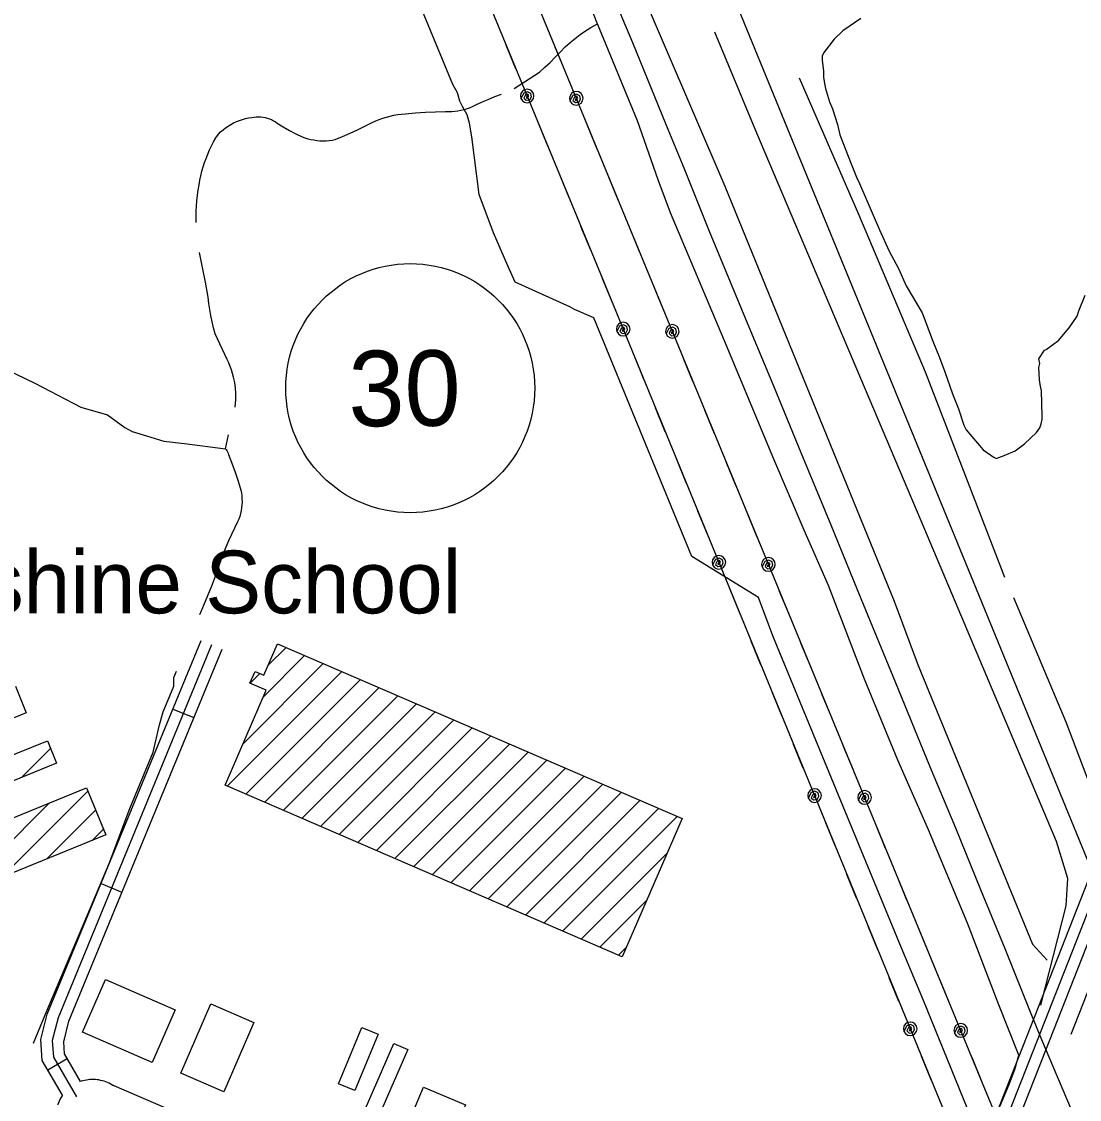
# Model space of a CAD drawing. Extents: x 3329332 to 3367211, y 631066 to 656469.
# Drawn here: x 3347758 to 3349160, y 652972 to 654400 of the extents above; entities that cross this region are included whole.
import ezdxf

# ---------------------------------------------------------------- set-up
doc = ezdxf.new("R2010")
doc.units = 0
for name, color, linetype in [('V-BLDG-IDEN', 7, 'Continuous'), ('V-BLDG-OTLN', 7, 'Continuous'), ('V-RAIL-TRAK', 7, 'Continuous'), ('V-ROAD-CNTR', 7, 'Continuous'), ('V-ROAD-IDEN', 7, 'Continuous'), ('V-SITE-VEGE', 7, 'Continuous'), ('V-TOPO-SHOR', 7, 'Continuous'), ('V-UTIL-LINE', 7, 'Continuous')]:
    doc.layers.add(name, color=color, linetype=linetype)

msp = doc.modelspace()

# ---------------------------------------------------------------- linework, layer by layer
at = {"layer": 'V-BLDG-OTLN'}
for p, q in [((3348085.1, 653547.4), (3348108.7, 653571)), ((3348078.7, 653505.6), (3348133.4, 653560.3)), ((3348030.8, 653387), (3348182.8, 653539)), ((3348051.8, 653443.4), (3348158.1, 653549.6)), ((3348055.5, 653376.4), (3348207.5, 653528.3)), ((3348061.1, 653523.4), (3348074.2, 653536.4)), ((3348080.2, 653365.7), (3348232.2, 653517.7)), ((3348104.9, 653355), (3348256.9, 653507)), ((3348129.6, 653344.4), (3348281.6, 653496.3)), ((3348154.3, 653333.7), (3348306.2, 653485.7)), ((3348179, 653323), (3348330.9, 653475)), ((3348203.7, 653312.4), (3348355.6, 653464.3)), ((3348228.4, 653301.7), (3348380.3, 653453.7)), ((3348253.1, 653291.1), (3348405, 653443)), ((3347758.7, 653399.1), (3347796.7, 653437.1)), ((3348277.7, 653280.4), (3348429.7, 653432.3)), ((3348302.4, 653269.7), (3348454.4, 653421.7)), ((3348327.1, 653259.1), (3348479.1, 653411)), ((3348351.8, 653248.4), (3348503.8, 653400.4)), ((3348376.5, 653237.7), (3348528.5, 653389.7)), ((3347732.2, 653266.5), (3347846.2, 653380.4)), ((3348401.2, 653227.1), (3348553.2, 653379)), ((3348425.9, 653216.4), (3348577.9, 653368.4)), ((3347672.4, 653242), (3347795.3, 653365)), ((3347791.9, 653290.9), (3347856.4, 653355.3)), ((3348450.6, 653205.8), (3348602.5, 653357.7)), ((3348475.3, 653195.1), (3348627.2, 653347)), ((3347851.7, 653315.3), (3347866.7, 653330.2)), ((3348500, 653184.4), (3348613.7, 653298.2)), ((3348524.7, 653173.8), (3348586.9, 653236)), ((3348549.4, 653163.1), (3348560, 653173.7))]:
    msp.add_line(p, q, dxfattribs=at)
for points in [[(3348633.6, 653344.3), (3348554.4, 653160.9), (3348028, 653388.3), (3348082.4, 653514.2), (3348060.9, 653523.4), (3348067.7, 653539.2), (3348079.4, 653534.2), (3348097.4, 653575.9)], [(3347961.9, 653091), (3347931.5, 653021), (3347839, 653061.2), (3347869.4, 653131.2)], [(3347969.4, 653007.1), (3348009.1, 653098.6), (3348066.1, 653073.9), (3348026.4, 652982.4)], [(3348230.8, 653058.4), (3348200.1, 652983.9), (3348178.4, 652992.9), (3348209.1, 653067.4)], [(3348210, 652900.6), (3348191.6, 652908.6), (3348251.6, 653046.4), (3348270, 653038.4)], [(3348307.8, 652872.6), (3348251.9, 652896.1), (3348290.7, 652988.5), (3348346.6, 652965.1)]]:
    msp.add_lwpolyline(points, close=True, dxfattribs=at)
for points in [[(3347750.1, 653519.6), (3347764.5, 653484.4), (3347586.4, 653411.6)], [(3347603, 653370.9), (3347792.6, 653447.4), (3347804.3, 653417.7), (3347617, 653341.2)], [(3347634.2, 653299.1), (3347844.3, 653385), (3347869.8, 653322.7), (3347657.6, 653236)]]:
    msp.add_lwpolyline(points, dxfattribs=at)
at = {"layer": 'V-RAIL-TRAK'}
msp.add_lwpolyline([(3349202.3, 652830.4), (3349149.9, 652958.2), (3349131.3, 653002), (3349110.4, 653051.1), (3349097.1, 653083.5), (3349061.9, 653171.5), (3349029.7, 653249.6), (3348996.3, 653331.3), (3348961.9, 653413.5), (3348916.5, 653524.8), (3348871.1, 653635.3), (3348831, 653732.9), (3348791.3, 653828.8), (3348755.2, 653916.9), (3348720.3, 654000.4), (3348670.1, 654121.8), (3348637.1, 654203.5), (3348611.9, 654264.7), (3348568.3, 654371.9), (3348523.8, 654477.8), (3348478.8, 654587.8), (3348449, 654660.4)], dxfattribs=at)
at = {"layer": 'V-ROAD-CNTR'}
for p, q in [((3347958.8, 653489.3), (3347986.5, 653477.9)), ((3347863.5, 653258.2), (3347891.2, 653246.8)), ((3347792.8, 653011.4), (3347818.7, 653026.4))]:
    msp.add_line(p, q, dxfattribs=at)
for points in [[(3348890.1, 652554.7), (3348987.6, 652793.7), (3349357.8, 653734.5), (3349739.4, 654671.6)], [(3347836.6, 649939.1), (3348422, 651367.8), (3349001.5, 652788.1), (3349371.7, 653728.9), (3349753.3, 654665.9)], [(3347850.5, 649933.4), (3348435.9, 651362.1), (3349015.5, 652782.6), (3349385.7, 653723.3), (3349767.2, 654660.2)], [(3348607.1, 654663.7), (3348622.3, 654626.9), (3349428.4, 652661.2), (3350055.8, 651140.1)], [(3347812.3, 652977.6), (3347785.7, 653023.7), (3347783.7, 653051.3), (3347792.2, 653085.1), (3347996.2, 653580.1)], [(3348010, 653574.4), (3347806.5, 653080.4), (3347798.9, 653050), (3347800.4, 653028.2), (3347830.8, 652975.6)], [(3347836.4, 652995.8), (3347815.1, 653032.7), (3347814, 653048.6), (3347820.8, 653075.7), (3348023.9, 653568.7)], [(3347880, 652990.1), (3347878.4, 652991.2), (3347876.3, 652992.4), (3347874.2, 652993.5), (3347872.1, 652994.5), (3347869.9, 652995.4), (3347867.6, 652996.2), (3347865.3, 652996.9), (3347863, 652997.4), (3347860.7, 652997.9), (3347858.3, 652998.2), (3347856, 652998.5), (3347853.6, 652998.6), (3347851.2, 652998.6), (3347848.8, 652998.4), (3347846.5, 652998.2), (3347844.1, 652997.8), (3347841.8, 652997.4), (3347839.5, 652996.8), (3347837.2, 652996.1), (3347836.4, 652995.8)], [(3348890.1, 652554.7), (3347877.8, 652991.3)], [(3347812.3, 652977.6), (3347810.2, 652974.1), (3347809, 652972), (3347808, 652969.9), (3347807.1, 652967.7), (3347806.3, 652965.6), (3347806, 652964.6)]]:
    msp.add_lwpolyline(points, dxfattribs=at)
at = {"layer": 'V-ROAD-IDEN'}
msp.add_circle((3348273.3, 653914.4), 165, dxfattribs=at)
at = {"layer": 'V-SITE-VEGE'}
msp.add_lwpolyline([(3348870.6, 654404.3), (3348846.5, 654388), (3348835, 654376.7), (3348821.3, 654359.3), (3348819.2, 654354.1), (3348819.1, 654348.9), (3348821, 654334.4), (3348820.9, 654326.1), (3348822.8, 654315.7), (3348823.8, 654311.5), (3348828.8, 654293.9), (3348832.8, 654284.5), (3348839.8, 654263.6), (3348842.8, 654250.1), (3348857.8, 654211.6), (3348864.9, 654193.8), (3348868.9, 654185.5), (3348895.1, 654124), (3348908.2, 654095.8), (3348920.4, 654072.8), (3348930.5, 654049.9), (3348951.8, 654014.4), (3348965.9, 653976.9), (3348974.9, 653955), (3348982, 653936.2), (3348992, 653907.1), (3349000, 653887.2), (3349007, 653865.4), (3349010, 653859.1), (3349032.5, 653832.9), (3349042.8, 653825.5), (3349045.9, 653823.4), (3349050, 653821.3), (3349060.4, 653825.3), (3349075, 653831.3), (3349087.6, 653840.5), (3349103.3, 653855.9), (3349107.6, 653862), (3349109.7, 653867.2), (3349110.8, 653873.4), (3349110.9, 653877.6), (3349110.2, 653910.8), (3349108.3, 653919.1), (3349107.3, 653925.3), (3349106.5, 653941.9), (3349107.6, 653947.1), (3349106.6, 653953.3), (3349114, 653964.6), (3349116.1, 653965.7), (3349132.9, 653977.9), (3349141.3, 653988.2), (3349146.5, 653994.3), (3349157.1, 654009.7), (3349159.3, 654017), (3349167.8, 654037.6)], dxfattribs=at)
at = {"layer": 'V-TOPO-SHOR'}
msp.add_line((3348028.4, 653834.1), (3348032.3, 653852.8), dxfattribs=at)
for points in [[(3348934.8, 652665), (3348966.7, 652743.2), (3349000, 652827.6), (3349039.3, 652925.9), (3349066.6, 652991.1), (3349074.6, 653011.7), (3349080.1, 653030.9), (3349053.5, 653097.3), (3349012, 653205.8), (3348960, 653329.3), (3348919.7, 653421.8), (3348875.3, 653528.9), (3348827.6, 653652.9), (3348795.3, 653726.5), (3348754.1, 653823.5), (3348693.3, 653968.8), (3348618.4, 654146.6), (3348602, 654190.2), (3348574.6, 654268.6), (3348521.5, 654397.3), (3348521.3, 654397.9), (3348469.9, 654529.7), (3348439.4, 654597.5), (3348413.5, 654660.4)], [(3348485.3, 654660), (3348690.3, 654182.2), (3348914.5, 653632.1), (3348946.5, 653547.2), (3349098.1, 653177.6), (3349117.3, 653156.4)], [(3348411.2, 654311.5), (3348444.8, 654333.1), (3348451.9, 654339.5), (3348458.8, 654346), (3348465.6, 654352.8), (3348472.1, 654359.7), (3348478.5, 654366.8), (3348485.1, 654372.4), (3348491.8, 654377.7), (3348498.7, 654382.9), (3348505.7, 654387.9), (3348512.9, 654392.1), (3348521.5, 654397.3)], [(3349108.9, 653096.9), (3349142.7, 653228.7), (3349144.7, 653264.8), (3349129.7, 653313.7), (3348950.4, 653738.5), (3348732.6, 654252.4), (3348677.1, 654386.2)], [(3348788.6, 654325.7), (3348867.4, 654144.8), (3348955.7, 653936), (3349044.4, 653706.6), (3349061.1, 653663.9)], [(3347989.7, 654134.1), (3347989.6, 654141.3), (3347989.8, 654148.4), (3347990.1, 654155.6), (3347990.7, 654162.7), (3347991.5, 654169.9), (3347992.4, 654176.9), (3347993.6, 654184), (3347994.6, 654189.9), (3347995.9, 654195.8), (3347997.3, 654201.7), (3347998.9, 654207.5), (3348000.8, 654213.2), (3348002.8, 654218.9), (3348005, 654224.5), (3348007.4, 654230), (3348010, 654235.4), (3348012.8, 654240.7), (3348015.8, 654246), (3348019, 654251.1), (3348022, 654254), (3348025.2, 654256.7), (3348028.6, 654259.3), (3348032, 654261.6), (3348035.6, 654263.8), (3348039.3, 654265.8), (3348043.2, 654267.5), (3348047.1, 654269.1), (3348051.1, 654270.4), (3348055.1, 654271.5), (3348059.2, 654272.4), (3348063.4, 654273), (3348066.3, 654273.5), (3348069.2, 654273.9), (3348072.2, 654274), (3348075.1, 654273.9), (3348078.1, 654273.6), (3348081, 654273), (3348083.9, 654272.3), (3348086.7, 654271.3), (3348089.4, 654270.2), (3348092, 654268.8), (3348094.6, 654267.2), (3348097, 654265.5), (3348105, 654260.6), (3348113.2, 654255.9), (3348121.6, 654251.4), (3348130, 654247.2), (3348133.8, 654245.9), (3348137.7, 654244.8), (3348141.6, 654243.9), (3348145.6, 654243.2), (3348149.6, 654242.7), (3348153.6, 654242.3), (3348157.6, 654242.2), (3348161.7, 654242.3), (3348165.7, 654242.6), (3348169.7, 654243.1), (3348173.7, 654243.8), (3348183.7, 654247.9), (3348193.7, 654252.3), (3348203.6, 654256.8), (3348213.3, 654261.5), (3348223, 654266.4), (3348227.6, 654268.5), (3348232.3, 654270.4), (3348237.1, 654272.1), (3348242, 654273.6), (3348246.9, 654274.9), (3348251.8, 654276), (3348256.8, 654276.9), (3348261.8, 654277.5), (3348266.9, 654278), (3348280.2, 654279.1), (3348293.5, 654280), (3348306.8, 654280.6), (3348320.2, 654281), (3348324.2, 654280.9), (3348328.3, 654281), (3348332.3, 654281.3), (3348336.3, 654281.9), (3348340.3, 654282.6), (3348344.2, 654283.5), (3348348.1, 654284.7), (3348352, 654286), (3348355.7, 654287.6), (3348359.4, 654289.3), (3348368, 654293.3), (3348376.7, 654297), (3348385.6, 654300.6), (3348394.5, 654303.8)], [(3348041.1, 653889.3), (3348041.7, 653894.1), (3348042.1, 653899), (3348042.2, 653903.9), (3348042.2, 653908.8), (3348041.7, 653913.9), (3348041.1, 653918.9), (3348040.2, 653923.9), (3348039.1, 653928.8), (3348037.9, 653933.7), (3348036.4, 653938.6), (3348034.7, 653943.3), (3348032.8, 653948), (3348030.7, 653952.6), (3348014.9, 653986.5), (3348012.8, 653994.5), (3348010.9, 654002.5), (3348009.2, 654010.5), (3348007.7, 654018.6), (3348006.5, 654026.8), (3348005.5, 654034.9), (3348002, 654054.7), (3347998.2, 654074.4), (3347994.1, 654094.1)], [(3347492.4, 654033.8), (3347725.8, 653945), (3347776, 653921.2), (3347836.9, 653889.1), (3347872.2, 653879.1), (3347895.2, 653862.4), (3347904.7, 653856.9), (3347923.7, 653851.2), (3347946.8, 653844.1), (3347974, 653841), (3348028.4, 653834.1)], [(3348028.4, 653834.1), (3348029.2, 653833.2), (3348030.3, 653831.7), (3348031.2, 653830), (3348031.9, 653828.3), (3348032.4, 653826.5), (3348036.9, 653814.9), (3348041.1, 653803.1), (3348045.1, 653791.2), (3348048.8, 653779.3), (3348049.6, 653775.5), (3348050.1, 653771.6), (3348050.3, 653767.7), (3348050.4, 653763.8), (3348050.2, 653759.9), (3348049.8, 653756), (3348049.2, 653752.2), (3348048.4, 653748.4), (3348047.3, 653744.6), (3348046, 653740.9), (3348044.6, 653737.3), (3348040.4, 653729.1), (3348036.4, 653720.7), (3348032.6, 653712.3), (3348029, 653703.7), (3348025.6, 653695.1), (3348022.3, 653686.5), (3348019.3, 653677.7), (3348014.6, 653664.8), (3348009.8, 653652), (3348004.7, 653639.2), (3347999.4, 653626.6), (3347993.9, 653614)], [(3349072.7, 653637.2), (3349142.3, 653472.4), (3349178.3, 653377.1), (3349182.1, 653363.7), (3349185.3, 653355.1), (3349199.9, 653348.9)], [(3347774.2, 653046.8), (3347789.6, 653084.2), (3347816.4, 653148), (3347846.2, 653217.5), (3347874.5, 653284.6), (3347901.9, 653357.5), (3347932.8, 653432.3), (3347940.9, 653468.4), (3347946, 653485.7), (3347959.9, 653519.7), (3347960, 653531.3), (3347963.5, 653539.4)], [(3349149.4, 653058.7), (3349181.1, 653139.5), (3349195.9, 653154.4), (3349206.6, 653150.2), (3349260, 652999.4)]]:
    msp.add_lwpolyline(points, dxfattribs=at)
at = {"layer": 'V-UTIL-LINE'}
for points in [[(3348280.4, 654660.1), (3348528.6, 654058.4), (3349879.4, 650766.8)], [(3349947.4, 650765), (3349454, 651980.1), (3349114.1, 652794.4), (3348779, 653606), (3348344.2, 654660.2)], [(3349017.1, 652946.7), (3348953.7, 653103), (3348922, 653179.3), (3348754, 653586.3), (3348735, 653637.2), (3348646.5, 653691.5), (3348516.5, 654007.7), (3348491.2, 654018.6), (3348484.9, 654022.2), (3348412.3, 654054.8), (3348402.7, 654076.6), (3348383.7, 654120.2), (3348364.7, 654171.1), (3348355.1, 654247.4), (3348351.9, 654265.6), (3348348.7, 654276.5), (3348342.4, 654287.4), (3348339.2, 654294.7), (3348336, 654305.6), (3348329.7, 654316.5), (3348218.7, 654585.4)], [(3348413.4, 654337.6), (3348400.5, 654369)], [(3348478.5, 654334.5), (3348465.5, 654366)], [(3348428.3, 654301.5), (3348426.8, 654299.1), (3348429.1, 654299.2), (3348430.5, 654301.5), (3348429.1, 654304.1), (3348425.9, 654302.9), (3348424, 654298.7), (3348427.1, 654295.8), (3348431.9, 654296.3), (3348433.9, 654300.5), (3348433.1, 654304.9), (3348428.9, 654307.2), (3348423.7, 654305.4), (3348420, 654298.1), (3348421.9, 654295.2), (3348424.9, 654293.2), (3348428.3, 654292.5), (3348431.8, 654293.2), (3348434.7, 654295.1), (3348436.6, 654298.1), (3348437.3, 654301.5), (3348436.6, 654304.9), (3348434.7, 654307.9), (3348431.8, 654309.8), (3348428.3, 654310.5), (3348424.9, 654309.8), (3348422, 654307.9), (3348420, 654305), (3348419.3, 654301.5), (3348420, 654298.1)], [(3348493.4, 654298.5), (3348491.8, 654296.1), (3348494.1, 654296.1), (3348495.6, 654298.5), (3348494.1, 654301.1), (3348490.9, 654299.9), (3348489, 654295.6), (3348492.2, 654292.7), (3348497, 654293.3), (3348499, 654297.4), (3348498.2, 654301.8), (3348493.9, 654304.1), (3348488.7, 654302.3), (3348485, 654295), (3348487, 654292.1), (3348489.9, 654290.2), (3348493.3, 654289.5), (3348496.8, 654290.2), (3348499.7, 654292.1), (3348501.7, 654295), (3348502.4, 654298.5), (3348501.7, 654301.9), (3348499.7, 654304.8), (3348496.8, 654306.8), (3348493.4, 654307.5), (3348489.9, 654306.8), (3348487, 654304.8), (3348485.1, 654301.9), (3348484.4, 654298.5), (3348485, 654295)], [(3348456.2, 654234), (3348443.2, 654265.5)], [(3348521.2, 654231), (3348508.2, 654262.4)], [(3348484.4, 654165.6), (3348471.4, 654197.1)], [(3348549.4, 654162.6), (3348536.4, 654194)], [(3348512.6, 654097.2), (3348499.6, 654128.7)], [(3348577.6, 654094.2), (3348564.7, 654125.6)], [(3348540.8, 654028.8), (3348528.6, 654058.4), (3348527.8, 654060.2)], [(3348605.8, 654025.8), (3348592.9, 654057.2)], [(3348555.6, 653992.7), (3348554, 653990.3), (3348556.3, 653990.4), (3348557.8, 653992.7), (3348556.4, 653995.3), (3348553.2, 653994.1), (3348551.2, 653989.9), (3348554.4, 653986.9), (3348559.2, 653987.5), (3348561.2, 653991.7), (3348560.4, 653996.1), (3348556.1, 653998.3), (3348550.9, 653996.6), (3348547.2, 653989.3), (3348549.2, 653986.4), (3348552.1, 653984.4), (3348555.5, 653983.7), (3348559, 653984.4), (3348561.9, 653986.3), (3348563.9, 653989.2), (3348564.6, 653992.7), (3348563.9, 653996.1), (3348561.9, 653999), (3348559, 654001), (3348555.6, 654001.7), (3348552.1, 654001), (3348549.2, 653999.1), (3348547.3, 653996.2), (3348546.6, 653992.7), (3348547.2, 653989.3)], [(3348620.7, 653989.7), (3348619.1, 653987.3), (3348621.5, 653987.4), (3348622.9, 653989.7), (3348621.5, 653992.3), (3348618.3, 653991.1), (3348616.4, 653986.9), (3348619.5, 653983.9), (3348624.3, 653984.5), (3348626.3, 653988.7), (3348625.5, 653993.1), (3348621.3, 653995.3), (3348616.1, 653993.5), (3348612.4, 653986.3), (3348614.3, 653983.4), (3348617.3, 653981.4), (3348620.7, 653980.7), (3348624.1, 653981.4), (3348627.1, 653983.3), (3348629, 653986.2), (3348629.7, 653989.7), (3348629, 653993.1), (3348627.1, 653996.1), (3348624.2, 653998), (3348620.7, 653998.7), (3348617.3, 653998), (3348614.4, 653996.1), (3348612.4, 653993.2), (3348611.7, 653989.7), (3348612.4, 653986.3)], [(3348583.3, 653925.2), (3348570.4, 653956.6)], [(3348648.5, 653922.2), (3348635.6, 653953.7)], [(3348611.4, 653856.7), (3348598.5, 653888.2)], [(3348676.8, 653853.8), (3348663.8, 653885.2)], [(3348639.5, 653788.3), (3348626.5, 653819.7)], [(3348705, 653785.4), (3348692, 653816.8)], [(3348667.6, 653719.8), (3348654.6, 653751.3)], [(3348733.2, 653717), (3348720.2, 653748.4)], [(3348682.4, 653683.7), (3348680.8, 653681.3), (3348683.1, 653681.4), (3348684.6, 653683.7), (3348683.2, 653686.3), (3348680, 653685.1), (3348678, 653680.9), (3348681.2, 653678), (3348686, 653678.5), (3348688, 653682.7), (3348687.2, 653687.1), (3348682.9, 653689.3), (3348677.7, 653687.6), (3348674, 653680.3), (3348676, 653677.4), (3348678.9, 653675.4), (3348682.3, 653674.7), (3348685.8, 653675.4), (3348688.7, 653677.3), (3348690.7, 653680.2), (3348691.4, 653683.7), (3348690.7, 653687.1), (3348688.7, 653690.1), (3348685.8, 653692), (3348682.4, 653692.7), (3348678.9, 653692), (3348676, 653690.1), (3348674.1, 653687.2), (3348673.4, 653683.7), (3348674, 653680.3)], [(3348748.1, 653680.9), (3348746.5, 653678.5), (3348748.8, 653678.6), (3348750.3, 653681), (3348748.8, 653683.5), (3348745.6, 653682.4), (3348743.7, 653678.1), (3348746.9, 653675.2), (3348751.7, 653675.8), (3348753.7, 653679.9), (3348752.9, 653684.3), (3348748.6, 653686.6), (3348743.4, 653684.8), (3348739.7, 653677.5), (3348741.7, 653674.6), (3348744.6, 653672.6), (3348748, 653671.9), (3348751.5, 653672.6), (3348754.4, 653674.6), (3348756.4, 653677.5), (3348757.1, 653680.9), (3348756.4, 653684.4), (3348754.4, 653687.3), (3348751.5, 653689.2), (3348748.1, 653689.9), (3348744.6, 653689.3), (3348741.7, 653687.3), (3348739.8, 653684.4), (3348739.1, 653681), (3348739.7, 653677.5)], [(3348710.1, 653616.2), (3348697.2, 653647.6)], [(3348775.9, 653613.5), (3348762.9, 653644.9)], [(3348738.2, 653547.7), (3348725.3, 653579.2)], [(3348804.1, 653545.1), (3348791.2, 653576.5)], [(3348766.3, 653479.3), (3348753.3, 653510.7)], [(3348832.4, 653476.7), (3348819.4, 653508.1)], [(3348794.3, 653410.8), (3348781.4, 653442.3)], [(3348860.6, 653408.3), (3348847.6, 653439.7)], [(3348809.2, 653374.7), (3348807.6, 653372.3), (3348809.9, 653372.4), (3348811.4, 653374.7), (3348810, 653377.3), (3348806.8, 653376.2), (3348804.8, 653371.9), (3348808, 653369), (3348812.8, 653369.5), (3348814.8, 653373.7), (3348814, 653378.1), (3348809.7, 653380.4), (3348804.5, 653378.6), (3348800.8, 653371.3), (3348802.8, 653368.4), (3348805.7, 653366.4), (3348809.1, 653365.7), (3348812.6, 653366.4), (3348815.5, 653368.3), (3348817.5, 653371.2), (3348818.2, 653374.7), (3348817.5, 653378.1), (3348815.5, 653381.1), (3348812.6, 653383), (3348809.2, 653383.7), (3348805.7, 653383), (3348802.8, 653381.1), (3348800.9, 653378.2), (3348800.2, 653374.7), (3348800.8, 653371.3)], [(3348875.5, 653372.2), (3348873.9, 653369.8), (3348876.3, 653369.9), (3348877.7, 653372.2), (3348876.3, 653374.8), (3348873.1, 653373.6), (3348871.2, 653369.4), (3348874.3, 653366.5), (3348879.1, 653367), (3348881.1, 653371.2), (3348880.3, 653375.6), (3348876.1, 653377.8), (3348870.9, 653376.1), (3348867.2, 653368.8), (3348869.1, 653365.9), (3348872.1, 653363.9), (3348875.5, 653363.2), (3348878.9, 653363.9), (3348881.9, 653365.8), (3348883.8, 653368.8), (3348884.5, 653372.2), (3348883.8, 653375.6), (3348881.9, 653378.6), (3348879, 653380.5), (3348875.5, 653381.2), (3348872.1, 653380.5), (3348869.1, 653378.6), (3348867.2, 653375.7), (3348866.5, 653372.2), (3348867.2, 653368.8)], [(3348836.9, 653307.2), (3348824, 653338.6)], [(3348903.4, 653304.7), (3348890.4, 653336.2)], [(3348865, 653238.7), (3348852.1, 653270.2)], [(3348931.6, 653236.3), (3348918.6, 653267.8)], [(3348893.1, 653170.3), (3348880.1, 653201.7)], [(3348959.9, 653167.9), (3348946.9, 653199.4)], [(3348921.1, 653101.8), (3348908.2, 653133.3)], [(3348988.1, 653099.5), (3348975.1, 653131)], [(3348936, 653065.7), (3348934.4, 653063.3), (3348936.7, 653063.4), (3348938.2, 653065.7), (3348936.8, 653068.3), (3348933.6, 653067.2), (3348931.6, 653062.9), (3348934.8, 653060), (3348939.6, 653060.6), (3348941.6, 653064.7), (3348940.8, 653069.1), (3348936.5, 653071.4), (3348931.3, 653069.6), (3348927.6, 653062.3), (3348929.6, 653059.4), (3348932.5, 653057.4), (3348935.9, 653056.7), (3348939.4, 653057.4), (3348942.3, 653059.3), (3348944.3, 653062.3), (3348945, 653065.7), (3348944.3, 653069.1), (3348942.3, 653072.1), (3348939.4, 653074), (3348936, 653074.7), (3348932.5, 653074), (3348929.6, 653072.1), (3348927.7, 653069.2), (3348927, 653065.8), (3348927.6, 653062.3)], [(3349003, 653063.5), (3349001.4, 653061.1), (3349003.7, 653061.2), (3349005.2, 653063.5), (3349003.8, 653066.1), (3349000.6, 653064.9), (3348998.7, 653060.6), (3349001.8, 653057.7), (3349006.6, 653058.3), (3349008.6, 653062.5), (3349007.8, 653066.9), (3349003.6, 653069.1), (3348998.4, 653067.3), (3348994.7, 653060.1), (3348996.6, 653057.1), (3348999.5, 653055.2), (3349003, 653054.5), (3349006.4, 653055.2), (3349009.3, 653057.1), (3349011.3, 653060), (3349012, 653063.5), (3349011.3, 653066.9), (3349009.4, 653069.9), (3349006.4, 653071.8), (3349003, 653072.5), (3348999.5, 653071.8), (3348996.6, 653069.9), (3348994.7, 653066.9), (3348994, 653063.5), (3348994.7, 653060.1)], [(3348963.7, 652998.2), (3348950.8, 653029.6)], [(3349030.8, 652996), (3349017.9, 653027.5)]]:
    msp.add_lwpolyline(points, dxfattribs=at)

# ---------------------------------------------------------------- texts
at = {"layer": 'V-BLDG-IDEN'}
msp.add_text('Sunshine School', height=83, dxfattribs=at).set_placement((3347508, 653616.1))
at = {"layer": 'V-ROAD-IDEN'}
msp.add_text('30', height=100, rotation=0.3916, dxfattribs=at).set_placement((3348191.7, 653863.8))

doc.saveas('drawing.dxf')
